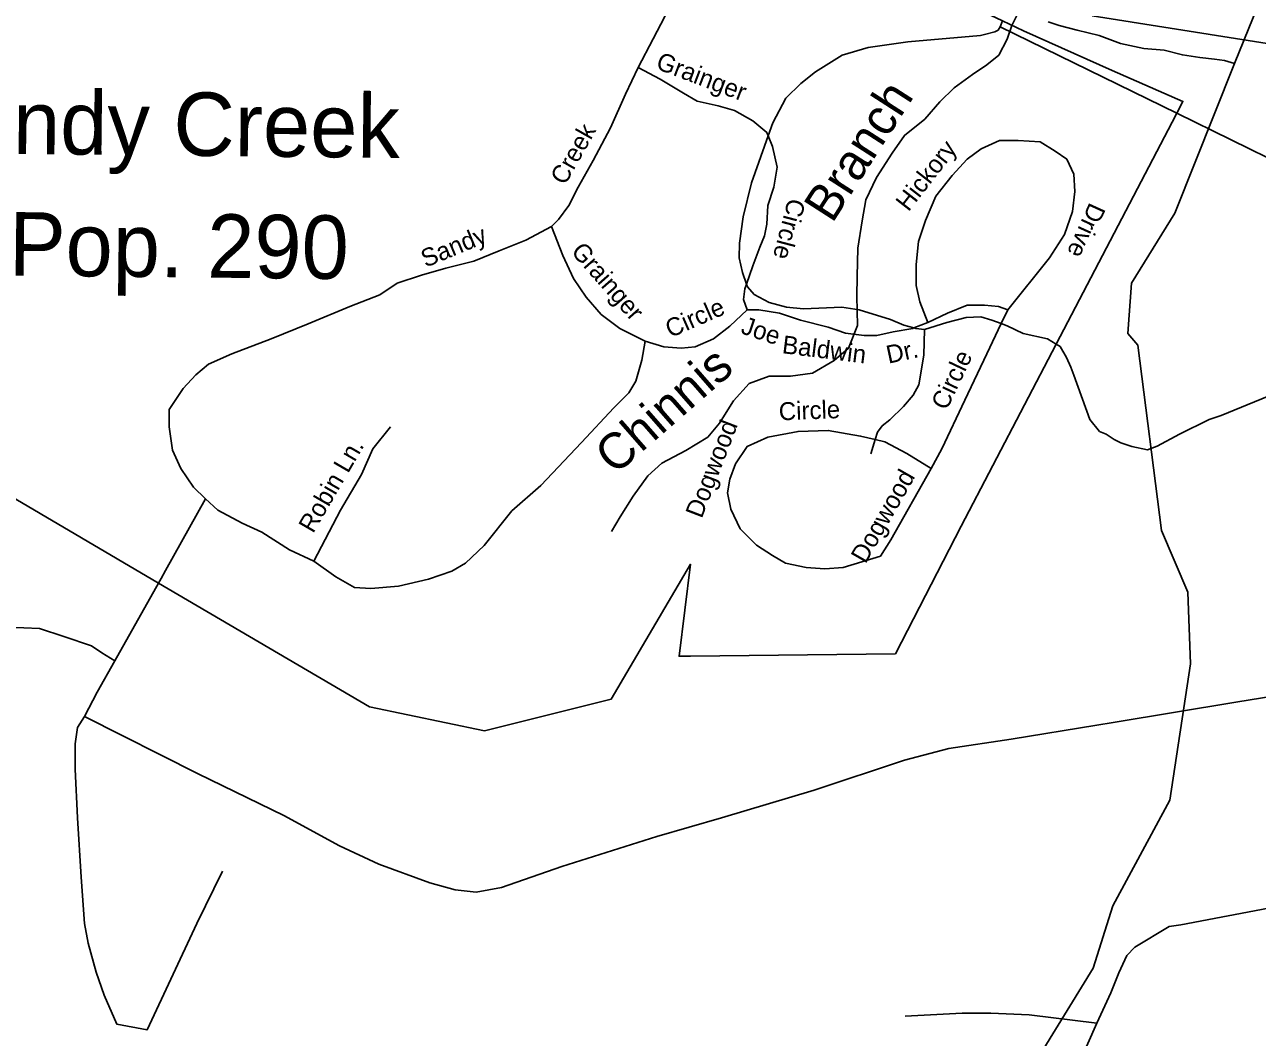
# Model space of a CAD drawing. Extents: x 2225501 to 2309677, y 165449 to 227696.
# Drawn here: x 2252503 to 2257649, y 192432 to 196661 of the extents above; entities that cross this region are included whole.
import ezdxf

# ---------------------------------------------------------------- set-up
doc = ezdxf.new("R2010")
doc.units = 0
for name, color, linetype in [('Old_Level_3', 7, 'Continuous'), ('Old_Level_46', 7, 'Continuous'), ('P_HYD_Drop_Inlet_Box_Type_A_48_Dia-Bottom_CELL', 7, 'Continuous'), ('P_HYD_Endwall_838_01_48_Dia_Single_CELL', 7, 'Continuous'), ('P_HYD_RipRap_Pad_876_02_24in_Outlet_With_Ditch_CELL', 7, 'Continuous'), ('P_HYD_RipRap_Pad_876_02_36in_Outlet_With_Ditch-Top_CELL', 7, 'Continuous'), ('Prop Support', 7, 'Continuous'), ('Scratch_Level_1', 7, 'Continuous'), ('Typical Terminator CELL', 7, 'Continuous')]:
    doc.layers.add(name, color=color, linetype=linetype)

msp = doc.modelspace()

# ---------------------------------------------------------------- linework, layer by layer
at = {"layer": 'Old_Level_3'}
for p, q in [((2256575.3, 196652.4), (2256585.6, 196677.3)), ((2257312.8, 196291), (2256575.3, 196652.4)), ((2259308.7, 195312.8), (2257312.8, 196291)), ((2256607.4, 195470.2), (2256580.2, 195412.6)), ((2256215.3, 195394.5), (2256273.7, 195417)), ((2256054.1, 194928.3), (2256036, 194868.8)), ((2253091.5, 194382), (2253258.5, 194681.5)), ((2252878.9, 194004.2), (2253061.8, 194329))]:
    msp.add_line(p, q, dxfattribs=at)
for points in [[(2255216.7, 197329.9), (2255147, 197202.3), (2255108.3, 197124.9), (2255098.6, 197062), (2255103.4, 196984.6), (2255132.4, 196912), (2255151.8, 196853.9), (2255176, 196786.2), (2255190.5, 196742.7), (2255176, 196694.3), (2255127.6, 196602.3), (2255064.7, 196481.4)], [(2256510.8, 196619.9), (2256553.7, 196630.3), (2256567.4, 196638.4), (2256575.3, 196652.4)], [(2255607.4, 196196.3), (2255627.1, 196251), (2255680.3, 196353.4), (2255743.7, 196415.9), (2255805.2, 196464.3), (2255916.5, 196533.1), (2256024.3, 196566), (2256189.9, 196589.4), (2256493.8, 196615.8), (2256510.8, 196619.9)], [(2255064.7, 196481.4), (2255011.5, 196370.1), (2254948.7, 196229.8), (2254876.1, 196094.3), (2254813.3, 195983), (2254774.6, 195905.6), (2254731.1, 195847.6), (2254702, 195818.5)], [(2255064.7, 196481.4), (2255156.6, 196433), (2255253.3, 196374.9), (2255311.4, 196341.1), (2255398.4, 196321.7), (2255466.1, 196302.4), (2255543.5, 196258.8), (2255601.5, 196210.4), (2255607.4, 196196.3)], [(2255516.7, 195577.5), (2255500.1, 195626.2), (2255485.7, 195687.9), (2255487.1, 195748.1), (2255502.3, 195858.1), (2255537, 196000.2), (2255607.4, 196196.3)], [(2255607.4, 196196.3), (2255625.7, 196152.4), (2255645.1, 196065.3), (2255630.6, 195983), (2255606.4, 195905.6), (2255601.5, 195828.2), (2255591.9, 195779.8), (2255572.5, 195731.5), (2255543.5, 195654), (2255516.7, 195577.5)], [(2256273.7, 195417), (2256239.9, 195504.1), (2256225.4, 195571.8), (2256225.4, 195658.9), (2256235.1, 195755.6), (2256264.1, 195842.7), (2256307.6, 195944.3), (2256375.3, 196031.4), (2256438.2, 196099.2), (2256496.2, 196142.7), (2256573.6, 196176.6), (2256651, 196176.6), (2256742.8, 196171.7), (2256805.7, 196133), (2256854.1, 196099.2), (2256883.1, 196036.3), (2256887.9, 195963.7), (2256878.2, 195881.4), (2256844.4, 195784.7), (2256781.5, 195687.9), (2256607.4, 195470.2)], [(2254702, 195818.5), (2254595.7, 195760.5), (2254484.4, 195716.9), (2254378, 195673.4), (2254262, 195644.4), (2254160.4, 195615.3), (2254058.9, 195581.5), (2253986.3, 195533.1), (2253860.6, 195484.7), (2253686.5, 195412.1), (2253531.7, 195349.2), (2253367.3, 195286.3), (2253270.6, 195242.8), (2253217.4, 195199.2), (2253164.2, 195141.2), (2253106.2, 195054.1), (2253106.2, 194981.5), (2253120.7, 194884.8), (2253154.5, 194807.3), (2253207.7, 194729.9), (2253258.5, 194681.5)], [(2254702, 195818.5), (2254750.4, 195697.6), (2254793.9, 195600.8), (2254847.1, 195523.4), (2254910, 195450.8), (2254987.4, 195392.8), (2255093.8, 195339.6)], [(2255516.7, 195577.5), (2255509.7, 195557.3), (2255504.8, 195513.7), (2255519.3, 195470.2)], [(2256215.3, 195394.5), (2256173.7, 195405.8), (2256117.5, 195429.3), (2255987.2, 195470.2), (2255915.2, 195481.6), (2255755.3, 195474.3), (2255683.3, 195481.7), (2255611.1, 195501.1), (2255548.9, 195534.5), (2255520.6, 195566.3), (2255516.7, 195577.5)], [(2255093.8, 195339.6), (2255171.1, 195315.4), (2255243.7, 195310.5), (2255301.7, 195315.4), (2255379.1, 195349.2), (2255446.8, 195402.5), (2255519.3, 195470.2)], [(2255519.3, 195470.2), (2255567.7, 195470.2), (2255654.7, 195455.7), (2255741.8, 195426.6), (2255857.8, 195397.6), (2255930.4, 195373.4), (2256007.8, 195363.7), (2256061, 195363.7), (2256128.7, 195378.3), (2256210.9, 195392.8), (2256215.3, 195394.5)], [(2256273.7, 195417), (2256356, 195455.7), (2256438.2, 195489.5), (2256510.7, 195489.5), (2256568.7, 195484.7), (2256607.4, 195470.2)], [(2259253.6, 195274.6), (2258846.1, 195463.5), (2258826.1, 195469.5), (2258796.2, 195465), (2258750.3, 195452.7), (2257916.9, 195182.1), (2257777.1, 195143), (2257498.2, 195028.6), (2257448.5, 195012.2), (2257324.9, 194951.2), (2257231.3, 194900.5), (2257191.5, 194886.3), (2257125.4, 194899.7), (2257079.3, 194915.2), (2257051.2, 194929.2), (2257019, 194950.8), (2256991, 194962.5), (2256950.6, 195012.3), (2256883.3, 195197.4)], [(2256580.2, 195412.6), (2256541.4, 195426.8), (2256495.3, 195440.3), (2256433.4, 195437.9), (2256353.4, 195417.3), (2256259.7, 195388.5)], [(2256259.7, 195388.5), (2256256.6, 195280.4), (2256235.8, 195156.4), (2256212, 195114.1), (2256172.4, 195065.9), (2256115, 195011.4), (2256083.1, 194985.2), (2256063.4, 194959), (2256054.1, 194928.3)], [(2256259.7, 195388.5), (2256223.8, 195392.2), (2256215.3, 195394.5)], [(2256580.2, 195412.6), (2256520.4, 195286.3), (2256428.5, 195092.8), (2256331.8, 194889.6), (2256288.3, 194807.3)], [(2256809.6, 195327.1), (2256774, 195348.7), (2256671.7, 195371.9), (2256605.5, 195403.3), (2256580.2, 195412.6)], [(2253710.7, 194420.3), (2253802.5, 194355), (2253879.9, 194311.4), (2253947.6, 194306.6), (2254063.7, 194316.3), (2254189.4, 194345.3), (2254286.1, 194379.2), (2254344.2, 194413), (2254421.6, 194485.6), (2254537.6, 194630.7), (2254658.5, 194737.2), (2254827.8, 194916.2), (2254963.2, 195061.4), (2255026.1, 195124.3), (2255055.1, 195172.6), (2255079.3, 195259.7), (2255093.8, 195339.6)], [(2256883.3, 195197.4), (2256870.9, 195231.4), (2256852.5, 195271.4), (2256826.2, 195317.1), (2256809.6, 195327.1)], [(2253710.7, 194420.3), (2253821.9, 194633.2), (2253908.9, 194783.2), (2253957.3, 194889.6), (2254029.8, 194981.5)], [(2256054.1, 194928.3), (2255993.3, 194942.8), (2255857.8, 194967), (2255732.1, 194962.2), (2255606.4, 194938), (2255519.3, 194899.3), (2255471, 194826.7), (2255446.8, 194763.8), (2255437.1, 194705.7), (2255451.6, 194638), (2255490.3, 194555.8), (2255558, 194488), (2255625.7, 194444.5), (2255678.9, 194413), (2255766, 194393.7), (2255843.3, 194388.8), (2255920.7, 194393.7), (2255998.1, 194417.9), (2256075.5, 194442.1), (2256119, 194509.8), (2256288.3, 194807.3)], [(2256288.3, 194807.3), (2256186.7, 194870.2), (2256094.8, 194918.6), (2256054.1, 194928.3)], [(2253258.5, 194681.5), (2253309.3, 194633.2), (2253410.8, 194579.9), (2253493, 194541.2), (2253609.1, 194468.7), (2253710.7, 194420.3)], [(2253061.8, 194329), (2253072.3, 194347.7), (2253091.5, 194382)], [(2251984.2, 194159), (2252216.3, 194154.2), (2252434, 194144.5), (2252564.5, 194139.7), (2252666.1, 194105.8), (2252782.2, 194067.1), (2252825.7, 194038.1), (2252878.9, 194004.2)], [(2259203.4, 194092.1), (2258759.5, 194026), (2258159.8, 193929.2), (2257560.1, 193832.4), (2257047.4, 193746.9)], [(2252753.1, 193772), (2252806.3, 193873.6), (2252878.9, 194004.2)], [(2252753.1, 193772), (2252724.1, 193726), (2252714.4, 193658.3), (2252714.4, 193551.8), (2252724.1, 193348.6), (2252738.6, 193101.9), (2252753.1, 192908.3), (2252767.6, 192826.1), (2252801.5, 192705.1), (2252835.3, 192608.3), (2252888.5, 192487.4), (2253014.3, 192463.2), (2253222.2, 192908.3), (2253328.6, 193126)], [(2257047.4, 193746.9), (2256979.8, 193735.7), (2256621.9, 193677.6), (2256360.8, 193638.9), (2256177, 193590.5), (2255799.8, 193464.7), (2255412.9, 193348.6), (2255142.1, 193271.2), (2254745.6, 193145.4), (2254494.1, 193058.3), (2254387.7, 193039), (2254300.7, 193048.6), (2254194.3, 193077.7), (2253981.5, 193155.1), (2253817.1, 193232.5), (2253584.9, 193358.3), (2253227.1, 193532.5), (2252753.1, 193772)], [(2258925, 193149.1), (2258878.8, 193162.8), (2258829, 193160.3), (2258098.2, 193036.4), (2257724.9, 192977.3), (2257329.5, 192902.2), (2257281.6, 192895.8), (2257138.4, 192808.6), (2257104.7, 192774.4), (2257071.3, 192702.1), (2257038.1, 192618), (2256979, 192491.4)], [(2256979, 192491.4), (2256697, 192527), (2256537, 192533.8), (2256417, 192532.9), (2256179.2, 192520.9)], [(2256979, 192491.4), (2256855.4, 192212.6), (2256649, 191771), (2256208, 190953.7), (2255891, 190343.5), (2255694.1, 189986)]]:
    msp.add_lwpolyline(points, dxfattribs=at)
at = {"layer": 'Old_Level_46'}
msp.add_lwpolyline([(2256960.1, 196697.4), (2259291.8, 196328.6), (2260129, 196210.1)], dxfattribs=at)
at = {"layer": 'P_HYD_Endwall_838_01_48_Dia_Single_CELL'}
msp.add_lwpolyline([(2256494.5, 197038.7), (2256364.8, 196783), (2256585.5, 196677.3), (2256673, 196635.5), (2257043.5, 196469), (2257338.8, 196340.6), (2257312.8, 196291), (2257293.5, 196254.1), (2256809.5, 195327.1), (2256412.5, 194566.7), (2256138.2, 194034.5), (2255283, 194024), (2255235, 194023.4), (2255283, 194408), (2254952, 193845.2), (2254422.2, 193712.7), (2253942.2, 193812), (2253061.8, 194329), (2252072.5, 194910)], dxfattribs=at)
at = {"layer": 'P_HYD_RipRap_Pad_876_02_36in_Outlet_With_Ditch-Top_CELL'}
msp.add_lwpolyline([(2256494.5, 197038.7), (2256364.8, 196783), (2256585.5, 196677.3), (2256673, 196635.5), (2257043.5, 196469), (2257338.8, 196340.6), (2257312.8, 196291), (2257293.5, 196254.1), (2256809.5, 195327.1), (2256412.5, 194566.7), (2256138.2, 194034.5), (2255283, 194024), (2255235, 194023.4), (2255283, 194408), (2254952, 193845.2), (2254422.2, 193712.7), (2253942.2, 193812), (2253061.8, 194329), (2252072.5, 194910)], dxfattribs=at)
at = {"layer": 'Prop Support'}
msp.add_lwpolyline([(2253671.7, 189944.7), (2254313.7, 190817.8), (2254496.6, 190961.9), (2254595.6, 190976.4), (2254787.8, 190946.4), (2255389.6, 190734.6), (2255672.8, 190702.8), (2255838.7, 190755.4), (2256455.7, 191809.4), (2256552.7, 192050.2), (2256963.8, 192721.2), (2257045.8, 192982), (2257283.7, 193423.5), (2257370.8, 193992.5), (2257359.7, 194291.2), (2257248.8, 194549.2), (2257150.8, 195322), (2257108.8, 195372), (2257123.7, 195581.6), (2257304.8, 195873.3), (2257554.7, 196498.2)], dxfattribs=at)
at = {"layer": 'Typical Terminator CELL'}
for points in [[(2257554.7, 196498.2), (2257688.6, 196833.4), (2257936.8, 197068.1), (2257976.7, 197228)], [(2254953.5, 194544.6), (2254988.7, 194605.2), (2255043.7, 194692), (2255104.8, 194776.9), (2255163.8, 194829.7), (2255263.5, 194883), (2255354.7, 194938.2), (2255404.2, 194996.9), (2255463, 195089.8), (2255528.2, 195162.7), (2255611.7, 195193.7), (2255699.8, 195192.8), (2255791.7, 195205.9), (2255883.2, 195259.1), (2255942.6, 195309.9), (2255979.5, 195404.5), (2255977.9, 195526.7), (2255978.9, 195608.9), (2255981.4, 195727.2), (2256000, 195841.7), (2256015, 195930.1), (2256059.7, 196022.8), (2256124.7, 196123.8), (2256175.8, 196198.5), (2256260.9, 196265.7), (2256324, 196338.6), (2256383.5, 196397.4), (2256460.8, 196452.4), (2256520.3, 196493.2), (2256569.7, 196533.9), (2256604.9, 196600.5), (2256624.4, 196656.8), (2256645.7, 196699.1)], [(2256776.2, 196672.6), (2256822.5, 196657.1), (2256896.7, 196637.9), (2256989.2, 196615), (2257077.8, 196581.9), (2257176, 196561), (2257260.3, 196554), (2257336.4, 196534.9), (2257408.7, 196523.7), (2257470.7, 196516.4), (2257512.7, 196510.9), (2257554.7, 196498.2)]]:
    msp.add_lwpolyline(points, dxfattribs=at)

# ---------------------------------------------------------------- texts
at = {"layer": 'P_HYD_Drop_Inlet_Box_Type_A_48_Dia-Bottom_CELL'}
for s, p in [('Sandy Creek', (2252019.7, 196126)), ('Pop. 290', (2252436.4, 195613.7))]:
    msp.add_text(s, height=265, rotation=359.3894, dxfattribs=at).set_placement(p)
at = {"layer": 'P_HYD_RipRap_Pad_876_02_24in_Outlet_With_Ditch_CELL'}
for s, rotation, p in [('Grainger', 339.1972, (2255133.9, 196478.7)), ('Creek', 60.5359, (2254759, 195987)), ('Hickory', 52.138, (2256192.9, 195876.9)), ('Circle', 255.257, (2255691.8, 195939.9)), ('Drive', 245.6273, (2256949.9, 195922.3)), ('Sandy', 22.6293, (2254177, 195645.5)), ('Grainger', 311.3346, (2254780.8, 195711.2)), ('Circle', 23.6394, (2255198.6, 195352)), ('Joe', 341.557, (2255489.2, 195373.2)), ('Baldwin', 352.877, (2255662.7, 195289.5)), ('Dr.', 12.0999, (2256109.1, 195245.1)), ('Circle', 64.6027, (2256352.2, 195046.8)), ('Circle', 2.2037, (2255652.9, 195008.4)), ('Dogwood', 68.9718, (2255329.6, 194596)), ('Robin Ln.', 59.8704, (2253707.2, 194533.6)), ('Dogwood', 60.3672, (2256013.7, 194407))]:
    msp.add_text(s, height=75, rotation=rotation, dxfattribs=at).set_placement(p)
at = {"layer": 'Scratch_Level_1'}
for s, rotation, p in [('Branch', 57.2324, (2255874.5, 195827.8)), ('Chinnis', 41.1291, (2254967.6, 194777))]:
    msp.add_text(s, height=150, rotation=rotation, dxfattribs=at).set_placement(p)

doc.saveas('drawing.dxf')
